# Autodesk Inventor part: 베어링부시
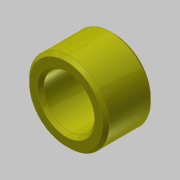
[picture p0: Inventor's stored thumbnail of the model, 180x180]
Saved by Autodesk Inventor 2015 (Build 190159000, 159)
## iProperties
Created: 2019-03
Part Number: 베어링부시
Material: 강철, 연강
Document SubType Name: Modeling
Designer: mduedu
Density: 1 g/cm^3
Appearance: 노란색
Author: mduedu
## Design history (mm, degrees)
sketch "스케치1"
  geometry: L1 (-7.5, 12.5)-(7.5, 12.5); L2 (7.5, 12.5)-(7.5, 8); L3 (7.5, 8)-(-7.5, 8); L4 (-7.5, 8)-(-7.5, 12.5); L5 (-7.5, 0)-(7.5, 0); 3 further points
  constraints: 10 end point, 2 midpoint, 2 parallel, 2 perpendicular, 2 vertical alignment, 1 coincident, 1 horizontal
  dimensions: "d0" = 16 diameter of L3 L5; "d2" = 25 diameter of L1 L5; "d3" = 15 distance of L1.start L1.end
revolve "회전1" sketch "스케치1" stored, may be unused: angle "d4" = 90 deg
chamfer "모따기1" distance "d5" = 1; stored, may be unused: second distance "d6" = 2, angle "d7" = 45 deg
chamfer "모따기2" distance "d8" = 1; stored, may be unused: second distance "d9" = 2, angle "d10" = 45 deg
node "솔리드1"
